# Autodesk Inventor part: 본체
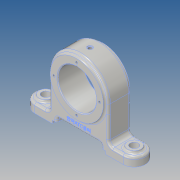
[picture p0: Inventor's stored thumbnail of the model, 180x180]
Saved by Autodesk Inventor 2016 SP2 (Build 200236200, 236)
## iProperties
Created: 2019-05
Part Number: 본체
Material: 알루미늄 6061
Document SubType Name: Modeling
Designer: EZ
Density: 2.7 g/cm^3
Appearance: 알루미늄 - 평지
Mass: 456.014 g
Surface Area: 318.8 cm^2
Volume: 168.894 cm^3
Author: EZ
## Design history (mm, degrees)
sketch "스케치1"
  geometry: L1 (-60, 0)-(60, 0); L2 (-60, -15)-(60, -15); L3 (60, 15)-(-60, 15); A1 r 15 centre (-60, 0) between (-60, 15) and (-60, -15); A2 r 15 centre (60, 0) between (60, -15) and (60, 15); 2 further points
  constraints: 8 end point, 4 point on circle, 4 tangent, 2 centre point, 1 coincident, 1 horizontal, 1 midpoint, 1 parallel
  dimensions: "d0" = 150 dimension on A2 A1; "d1" = 120 distance of L3.start L3.end
extrude "돌출1" new body sketch "스케치1" distance "d2" = 12; taper "d3" = 0 deg
sketch "스케치2"
  geometry: L1 (0, 0)-(0, 60); L2 (0, 0)-(0, 100); L3 (-40, 60)-(-40, 0); L4 (40, 60)-(40, 0); L5 (-40, 0)-(40, 0); L6 (60, 0)-(-60, 0) reference; A1 r 40 centre (0, 60) between (0, 100) and (-40, 60)
  constraints: 10 end point, 4 vertical, 3 point on circle, 1 centre point, 1 coincident, 1 collinear, 1 tangent
  dimensions: "d4" = 60 distance of L1.start L1.end; "d6" = 100 distance of L1.start L2.end
extrude "돌출2" join sketch "스케치2" stored distance "d7" = 30; taper "d8" = 0 deg
sketch "스케치3"
  geometry: L1 (-60, 0)-(60, 0) reference; C1 r 36 at (0, 60); 1 further point
  constraints: 1 centre point
  dimensions: "d9" = 72 diameter of C1; "d10" = 60 distance from line of L1 C1.centre
extrude "돌출3" join sketch "스케치3" stored distance "d11" = 36; taper "d12" = 0 deg
sketch "스케치4"
  geometry: C1 r 36 at (0, 0) reference; C2 r 26 at (0, 0); 1 further point
  constraints: 1 centre point, 1 coincident
  dimensions: "d13" = 52 diameter of C2
extrude "돌출4" cut sketch "스케치4" stored distance "d14" = 36; taper "d15" = 0 deg
sketch "스케치5" dims "d16" = 62
  geometry: L1 (0, 0)-(0, 31); C1 r 36 at (0, 0) reference; 1 further point
  constraints: 2 end point, 1 coincident, 1 vertical, 1 vertical alignment, 2 other
hole "구멍1" sketch "스케치5" at (0, 31) diameter "d17" = 3.242; stored, may be unused: countersink angle "d21" = 90 deg, drill point angle "d23" = 118 deg; dims "d18" = 6, "d19" = 4, "d20" = 2, "d22" = 8
sketch "스케치6"
  geometry: C1 r 9 at (60, 0); A1 r 15 centre (60, 0) between (60, -15) and (60, 15) reference; 1 further point
  constraints: 1 centre point, 1 coincident
  dimensions: "d27" = 18 diameter of C1
extrude "돌출5" join sketch "스케치6" distance "d28" = 3; taper "d29" = 0 deg
sketch "스케치7"
  geometry: C1 r 9 at (0, 0) reference; C2 r 5.5 at (0, 0); 1 further point
  constraints: 1 centre point, 1 coincident
  dimensions: "d30" = 11 diameter of C2
extrude "돌출6" cut sketch "스케치7" stored distance "d31" = 0; taper "d32" = 0 deg
node "작업 평면1"
sketch "스케치8"
  geometry: C1 r 1 at (0, 0); 1 further point
  constraints: 1 centre point, 1 coincident
  dimensions: "d34" = 2 diameter of C1
extrude "돌출7" cut sketch "스케치8" stored distance "d35" = 3; taper "d36" = 0 deg
sketch "스케치9"
  geometry: 1 further point
hole "구멍2" sketch "스케치9" at (0, 0) diameter "d37" = 4.917; stored, may be unused: countersink angle "d41" = 90 deg, drill point angle "d43" = 118 deg; dims "d38" = 8, "d39" = 7, "d40" = 1, "d42" = 10
fillet "모깎기1" dims "d44" = 3
fillet "모깎기3" dims "d46" = 3
chamfer "모따기1" distance "d49" = 1; stored, may be unused: second distance "d50" = 2, angle "d51" = 45 deg
sketch "스케치11"
  geometry: L1 (24, -4)-(96, -4); L2 (96, -4)-(96, 4); L3 (96, 4)-(24, 4); L4 (24, 4)-(24, -4); L5 (24, -4)-(96, 4); L6 (96, -4)-(24, 4); L7 (0, 0)-(120, 0) reference; 1 further point
  constraints: 12 end point, 2 midpoint, 2 parallel, 1 horizontal, 1 perpendicular
  dimensions: "d52" = 72 distance of L1.start L1.end; "d56" = 4 distance from line of L7 L3.end
extrude "돌출8" cut sketch "스케치11" stored distance "d54" = 0; taper "d55" = 0 deg
sketch "스케치12"
  geometry: L1 (60, 60)-(36, 60) reference; L2 (-30, 50)-(30, 50); L3 (30, 50)-(30, 70); L4 (30, 70)-(-30, 70); L5 (-30, 70)-(-30, 50); L6 (-30, 50)-(30, 70); L7 (30, 50)-(-30, 70); 1 further point
  constraints: 12 end point, 2 midpoint, 2 parallel, 1 horizontal, 1 perpendicular
  dimensions: "d57" = 60 distance of L2.start L2.end; "d58" = 10 distance between parallel lines of L1 L4
extrude "돌출9" cut sketch "스케치12" stored distance "d59" = 0; taper "d60" = 0 deg
fillet "모깎기7" dims "d66" = 3, "d67" = 6
fillet "모깎기8" dims "d68" = 3
sketch "스케치14"
  geometry: L1 (-63, 10)-(-9, 10) reference; 2 further points
  constraints: 1 vertical alignment, 1 other
  dimensions: "d69" = 7 distance from line of L1 point (-36, 17)
feature "엠보싱2" sketch "스케치14" dims "d0" = 150, "d1" = 120, "d9" = 72, "d70" = 0.5, "d71" = 0
sketch "스케치15"
  geometry: C1 r 1.5 at (0, 26); 2 further points
  constraints: 1 centre point, 1 vertical alignment, 1 other
  dimensions: "d72" = 3 diameter of C1
extrude "돌출10" cut sketch "스케치15" stored distance "d73" = 0; taper "d74" = 0 deg
node "솔리드1"
pattern_circular "원형 패턴1" dims angle "d25" = 360 deg
mirror "대칭1"
mirror "대칭2"
mirror "대칭3"
